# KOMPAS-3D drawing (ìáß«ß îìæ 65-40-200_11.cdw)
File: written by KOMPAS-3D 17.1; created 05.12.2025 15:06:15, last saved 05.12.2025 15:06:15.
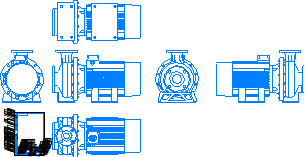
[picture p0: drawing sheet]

Sheet 1: A4, portrait

Title block, sheet 1: name: Насос МНС / 65-40-200_11; material: Сталь 10  ГОСТ 1050-88; mass: 182,92; sheets: 1; sheet format: A4

Views: Вид 1, Спереди, Проекционный вид 2, Проекционный вид 3, Проекционный вид 4, Проекционный вид 6
Referenced files in \\adlc.lan\data\АДЛ_ПКД\3D-модели\ADL production\Насосы ГРАНПАМП\Насосы ГРАНПАМП серии МНС\KOMPAS 3D\: Насос МНС 65-40-200_11.m3d
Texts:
  Andrey
  АДЛ
Dimensions and other numbers on the sheet: 1:1; 1; 65-40-200_11; 182,92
